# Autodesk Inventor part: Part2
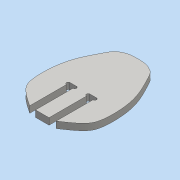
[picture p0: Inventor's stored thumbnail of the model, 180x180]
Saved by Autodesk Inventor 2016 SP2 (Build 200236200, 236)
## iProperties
Created: 2017-07
Part Number: Part2
Material: Generic
Document SubType Name: Modeling
Designer: Mohamed A.
Density: 1 g/cm^3
Appearance: Default
Author: Mohamed A.
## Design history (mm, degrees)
sketch "Sketch1"
  geometry: L1 (-128.97, 311.551)-(97.425, 311.551); L2 (97.425, 311.551)-(97.425, -8.689); L3 (97.425, -8.689)-(-128.97, -8.689); L4 (-128.97, -8.689)-(-128.97, 311.551); L5 (22.38, 44.504)-(11.38, 44.504); L6 (11.38, -24.605)-(0, -24.605); L7 (22.379, -23.388)-(49.93, -5.48); L8 (49.93, -5.48)-(59.237, 7.235); L9 (59.237, 7.235)-(61.268, 29.063); L10 (61.268, 29.063)-(59.237, 77.896); L11 (59.237, 77.896)-(36.481, 115.561); L12 (36.481, 115.561)-(31.916, 129.748); L13 (31.916, 129.748)-(20.958, 132.756); L14 (20.958, 132.756)-(14.372, 136.504); L15 (14.372, 136.504)-(0, 136.504); L16 (22.379, 38.504)-(22.379, -23.388); L17 (11.379, 38.504)-(11.38, -24.605); L18 (0, -27.323)-(0, 147.477); L19 (-22.379, -23.388)-(-49.93, -5.48); L20 (-49.93, -5.48)-(-59.237, 7.235); L21 (-59.237, 7.235)-(-61.268, 29.063); L22 (-61.268, 29.063)-(-59.237, 77.896); L23 (-59.237, 77.896)-(-36.481, 115.561); L24 (-36.481, 115.561)-(-31.916, 129.748); L25 (-31.916, 129.748)-(-20.958, 132.756); L26 (-20.958, 132.756)-(-14.372, 136.504); L27 (-14.372, 136.504)-(0, 136.504); L28 (-22.379, 38.504)-(-22.379, -23.388); L29 (-22.38, 44.504)-(-11.38, 44.504); L30 (-11.379, 38.504)-(-11.38, -24.605); L31 (-11.38, -24.605)-(0, -24.605); A1 r 3 centre (22.38, 41.504) between (22.379, 38.504) and (22.38, 44.504); A2 r 3 centre (11.38, 41.504) between (11.38, 44.504) and (11.379, 38.504); A3 r 3 centre (-22.38, 41.504) between (-22.38, 44.504) and (-22.379, 38.504); A4 r 3 centre (-11.38, 41.504) between (-11.379, 38.504) and (-11.38, 44.504); 2 further points; 1 other entity
  constraints: 16 symmetric about line, 14 end point, 8 point on circle, 4 centre point, 3 point on line, 2 coincident, 2 horizontal, 2 vertical, 1 perpendicular, 16 other
  dimensions: "d70" = 3 radius of A2; "d73" = 3 radius of A1; "d74" = 11 distance of L5.start L5.end; "d75" = 63.10935 distance of L17.start L6.start; "d76" = 61.89229 distance of L16.start L7.start; "d79" = 92 distance between parallel lines of L15 L5; "d87" = 11 distance between parallel lines of L16 L17 (derived); "d90" = 22.759 distance between parallel lines of L17 L30; "d91" = 22.759 distance of A4.centre A2.centre
extrude "Extrusion1" new body sketch "Sketch1" distance "d56" = 11; taper "d57" = 0 deg
body "Solid1"
node "Image1"
